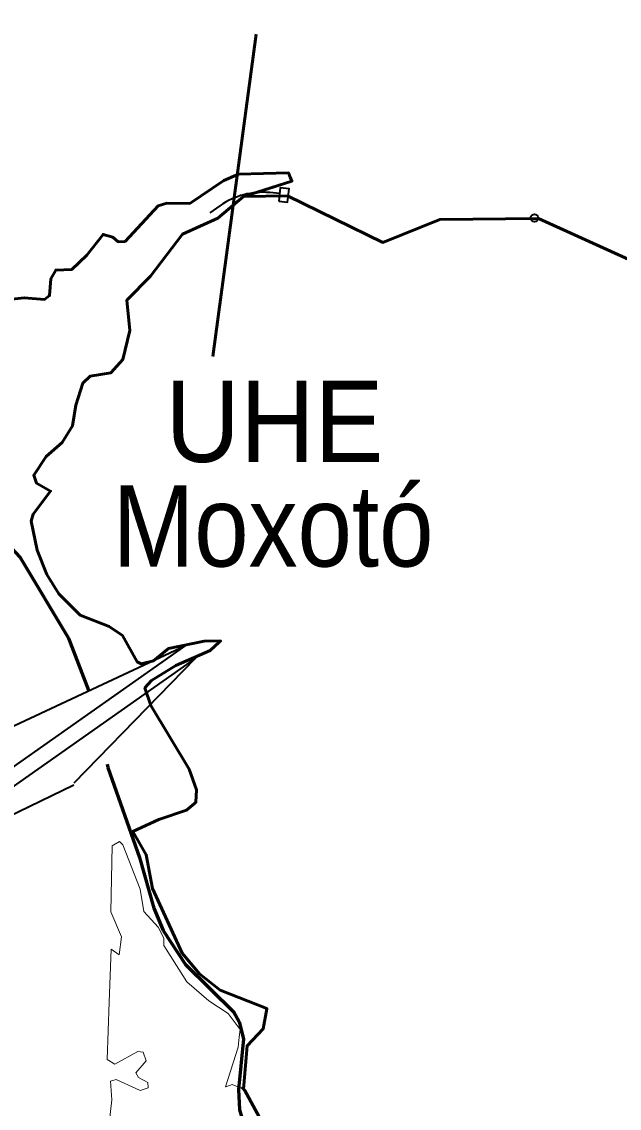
# Model space of a CAD drawing. Extents: x -1643653 to 4543381, y 1624270 to 13878484.
# Drawn here: x 587016 to 590692, y 8961924 to 8968607 of the extents above; entities that cross this region are included whole.
import ezdxf
from ezdxf.enums import TextEntityAlignment as Align

# ---------------------------------------------------------------- set-up
doc = ezdxf.new("R2010")
doc.units = 0
doc.header["$LTSCALE"] = 200
doc.linetypes.add('LONG_DASH_SHORT_DASH', pattern=[9.9, 6, -1.2, 1.5, -1.2])
for name, color, linetype, lineweight in [('1', 7, 'Continuous', 13), ('14', 7, 'Continuous', 13), ('25', 7, 'Continuous', 13), ('27', 7, 'Continuous', 53), ('28', 7, 'Continuous', 53), ('31', 7, 'Continuous', 53), ('60', 7, 'Continuous', 53), ('7', 7, 'LONG_DASH_SHORT_DASH', 60)]:
    doc.layers.add(name, color=color, linetype=linetype, lineweight=lineweight)
doc.layers.add('42', color=7, linetype='Continuous')

msp = doc.modelspace()

# ---------------------------------------------------------------- linework, layer by layer
at = {"layer": '1', "lineweight": 25}
msp.add_spline([(814781, 9009175.5), (814787.2, 9009173.4), (814796.9, 9009173.4), (814799.4, 9009172.4), (814805.1, 9009174.5), (814805.6, 9009176.5), (814811.7, 9009179.5), (814811.7, 9009179.5), (814801.5, 9009181), (814790.7, 9009181.5), (814784.1, 9009183.1), (814777.4, 9009185.1), (814778.4, 9009175.5)], degree=3, dxfattribs=at)
at = {"layer": '14', "lineweight": 40}
for p, q in [((588601.8, 8967550.6), (588542, 8967555.7)), ((588235.6, 8967474.9), (588172.7, 8967431.9))]:
    msp.add_line(p, q, dxfattribs=at)
msp.add_arc((588497.5, 8967102.9), 455, 84.39529, 125.14872, dxfattribs=at)
at = {"layer": '25', "lineweight": 35}
for p, q in [((588022.6, 8964770.6), (586135.6, 8963442.6)), ((586940.7, 8964263.4), (588022.6, 8964770.6)), ((588084.7, 8964692), (586189.9, 8963358.5)), ((587339.3, 8963925.5), (588084.7, 8964692)), ((586189.9, 8963358.5), (587335.7, 8963913.8))]:
    msp.add_line(p, q, dxfattribs=at)
at = {"layer": '25'}
for points in [[(586938.3, 8966898.9), (587031.7, 8966909.6), (587155.3, 8966899.2), (587187, 8966922.6), (587195.6, 8967026.5), (587225.2, 8967079.4), (587325, 8967083.9), (587416.4, 8967171), (587516.5, 8967298.4), (587577.2, 8967281.7), (587609.8, 8967253.9), (587652.2, 8967256), (587856.2, 8967474.6), (587908.7, 8967491.8), (588049.3, 8967489.5), (588259.2, 8967631.5), (588349.7, 8967670.3), (588657.3, 8967677.5), (588667.8, 8967651.8)], [(586938.3, 8966898.9), (587031.7, 8966909.6), (587155.3, 8966899.2), (587187, 8966922.6), (587195.6, 8967026.5), (587225.2, 8967079.4), (587325, 8967083.9), (587416.4, 8967171), (587516.5, 8967298.4), (587577.2, 8967281.7), (587609.8, 8967253.9), (587652.2, 8967256), (587856.2, 8967474.6), (587908.7, 8967491.8), (588049.3, 8967489.5), (588259.2, 8967631.5), (588349.7, 8967670.3), (588657.3, 8967677.5), (588667.8, 8967651.8)], [(588667.8, 8967651.8), (588678.2, 8967626.5), (588381.1, 8967532.1), (588221.7, 8967398.4), (588005.1, 8967300.6), (587807.3, 8967041.3), (587663.1, 8966894.9), (587682, 8966707.8), (587637.4, 8966529.4), (587563.2, 8966446.7), (587438, 8966427.4), (587392.7, 8966384.2), (587348.6, 8966249.6), (587329.2, 8966121.3), (587265.6, 8966019.6), (587165.8, 8965932.5), (587089.5, 8965818), (587106.5, 8965769), (587193.3, 8965719.9), (587087.2, 8965577.5), (587074.5, 8965534.6), (587110.7, 8965356.6), (587170.4, 8965207.5), (587244.3, 8965087.2), (587376.1, 8964957.5), (587554.3, 8964887.4), (587635.2, 8964832.1), (587726.7, 8964670.8), (587750.6, 8964658), (587826.4, 8964675), (587917.9, 8964751.3), (588138.8, 8964796.3), (588239.8, 8964798.6), (588239.8, 8964798.6), (588231, 8964790.9)], [(588667.8, 8967651.8), (588678.2, 8967626.5), (588381.1, 8967532.1), (588221.7, 8967398.4), (588005.1, 8967300.6), (587807.3, 8967041.3), (587663.1, 8966894.9), (587682, 8966707.8), (587637.4, 8966529.4), (587563.2, 8966446.7), (587438, 8966427.4), (587392.7, 8966384.2), (587348.6, 8966249.6), (587329.2, 8966121.3), (587265.6, 8966019.6), (587165.8, 8965932.5), (587089.5, 8965818), (587106.5, 8965769), (587193.3, 8965719.9), (587087.2, 8965577.5), (587074.5, 8965534.6), (587110.7, 8965356.6), (587170.4, 8965207.5), (587244.3, 8965087.2), (587376.1, 8964957.5), (587554.3, 8964887.4), (587635.2, 8964832.1), (587678.5, 8964757.6)], [(588231, 8964790.9), (588174.2, 8964740.5), (587964.7, 8964647.4), (587813.9, 8964556), (587773.6, 8964509.6), (587809.5, 8964400.9), (588045.3, 8964009.8), (588090.5, 8963883.4), (588087.9, 8963805.8), (588079.5, 8963798.7)], [(587773.6, 8964509.6), (587809.5, 8964400.9), (588045.3, 8964009.8), (588090.5, 8963883.4), (588087.9, 8963805.8), (588079.5, 8963798.7)], [(588079.5, 8963798.7), (588030.2, 8963757.2), (587858.5, 8963700), (587699.1, 8963625.3), (587781.9, 8963483), (587820, 8963275.3), (588002, 8962877.1), (588002, 8962877.1), (588108.8, 8962750.5), (588236.2, 8962650.7), (588523, 8962536.8)], [(588079.5, 8963798.7), (588030.2, 8963757.2), (587858.5, 8963700), (587699.1, 8963625.3), (587781.9, 8963483), (587820, 8963275.3), (588002, 8962877.1), (588002, 8962877.1), (588108.8, 8962750.5), (588236.2, 8962650.7), (588523, 8962536.8)], [(587982.8, 8962779.3), (587890.3, 8962924.4), (587890.1, 8962969.1), (587856.3, 8963036.9), (587766.9, 8963135.1), (587743.6, 8963270.8), (587637.1, 8963543.2), (587617, 8963563.8), (587571.7, 8963538.4), (587565.1, 8963131.3), (587628.8, 8962977.9), (587616.1, 8962866.9), (587565.4, 8962902.1), (587554.1, 8962576.4)], [(587982.8, 8962779.3), (587890.3, 8962924.4), (587890.1, 8962969.1), (587856.3, 8963036.9), (587766.9, 8963135.1), (587743.6, 8963270.8), (587637.1, 8963543.2), (587617, 8963563.8), (587571.7, 8963538.4), (587565.1, 8963131.3), (587628.8, 8962977.9), (587616.1, 8962866.9), (587565.4, 8962902.1), (587554.1, 8962576.4)], [(588354.5, 8962361.1), (588359.4, 8962408.8), (588285.5, 8962505.9), (588167, 8962584.2), (588032.3, 8962701.8), (587982.8, 8962779.3)], [(588354.5, 8962361.1), (588359.4, 8962408.8), (588285.5, 8962505.9), (588167, 8962584.2), (588032.3, 8962701.8), (587982.8, 8962779.3)], [(587554.1, 8962576.4), (587541.8, 8962223.9), (587588.7, 8962196), (587730.7, 8962272.2), (587762.7, 8962269), (587781.7, 8962215.1)], [(587554.1, 8962576.4), (587541.8, 8962223.9), (587588.7, 8962196), (587730.7, 8962272.2), (587762.7, 8962269), (587781.7, 8962215.1)], [(588523, 8962536.8), (588524.4, 8962536.2), (588501.9, 8962412.8), (588402.2, 8962308.3), (588381.1, 8962040.8), (588376.4, 8962042.8)], [(588523, 8962536.8), (588524.4, 8962536.2), (588501.9, 8962412.8), (588402.2, 8962308.3), (588381.1, 8962040.8), (588376.4, 8962042.8)], [(588271.6, 8962055.8), (588270.1, 8962055.2), (588348.1, 8962299.3), (588354.5, 8962361.1)], [(588271.6, 8962055.8), (588270.1, 8962055.2), (588348.1, 8962299.3), (588354.5, 8962361.1)], [(587781.7, 8962215.1), (587781.7, 8962215.1), (587718.2, 8962140.9), (587735, 8962113.3), (587792.4, 8962083.3), (587794.6, 8962050), (587745.5, 8962032.4), (587597.2, 8962100.2), (587563.1, 8962089.5), (587569.5, 8961975.7), (587540.2, 8961707.3), (587517.7, 8961501.6)], [(587781.7, 8962215.1), (587781.7, 8962215.1), (587718.2, 8962140.9), (587735, 8962113.3), (587792.4, 8962083.3), (587794.6, 8962050), (587745.5, 8962032.4), (587597.2, 8962100.2), (587563.1, 8962089.5), (587569.5, 8961975.7), (587540.2, 8961707.3), (587517.7, 8961501.6)], [(588376.4, 8962042.8), (588311.2, 8962069.4), (588271.6, 8962055.8), (588271.7, 8962060.3), (588271.6, 8962055.8)], [(588376.4, 8962042.8), (588311.2, 8962069.4), (588271.6, 8962055.8), (588271.7, 8962060.3), (588271.6, 8962055.8)]]:
    msp.add_lwpolyline(points, dxfattribs=at)
at = {"layer": '27'}
msp.add_line((592102.6, 8966532.4), (590195.5, 8967396.1), dxfattribs=at)
for points in [[(588667.8, 8967651.8), (588657.3, 8967677.5), (588349.7, 8967670.3), (588259.2, 8967631.5), (588049.3, 8967489.5), (587908.7, 8967491.8), (587856.2, 8967474.6), (587652.2, 8967256), (587609.8, 8967253.9), (587577.2, 8967281.7), (587516.5, 8967298.4), (587416.4, 8967171), (587325, 8967083.9), (587225.2, 8967079.4), (587195.6, 8967026.5), (587187, 8966922.6), (587155.3, 8966899.2), (587031.7, 8966909.6), (586938.3, 8966898.9)], [(588381.5, 8967532.2), (588678.2, 8967626.5), (588667.8, 8967651.8)], [(588239.8, 8964798.6), (588138.8, 8964796.3), (587917.9, 8964751.3), (587826.4, 8964675), (587750.6, 8964658), (587726.7, 8964670.8), (587635.2, 8964832.1), (587554.3, 8964887.4), (587376.1, 8964957.5), (587244.3, 8965087.2), (587170.4, 8965207.5), (587110.7, 8965356.6), (587074.5, 8965534.6), (587087.2, 8965577.5), (587193.3, 8965719.9), (587106.5, 8965769), (587089.5, 8965818), (587165.8, 8965932.5), (587265.6, 8966019.6), (587329.2, 8966121.3), (587348.6, 8966249.6), (587392.7, 8966384.2), (587438, 8966427.4), (587563.2, 8966446.7), (587637.4, 8966529.4), (587682, 8966707.8), (587663.1, 8966894.9), (587807.3, 8967041.3), (588005.1, 8967300.6), (588221.7, 8967398.4), (588381.1, 8967532.1), (588381.5, 8967532.2)], [(588381.5, 8967532.2), (588651.1, 8967535.2), (589236.5, 8967249.2), (589588.5, 8967391.6), (590195.5, 8967396.1), (592102.6, 8966532.4)], [(590195.5, 8967396.1), (589588.5, 8967391.6), (589236.5, 8967249.2), (588651.1, 8967535.2), (588381.5, 8967532.4)], [(588079.5, 8963798.7), (588087.9, 8963805.8), (588090.5, 8963883.4), (588045.3, 8964009.8), (587809.5, 8964400.9), (587773.6, 8964509.6), (587813.9, 8964556), (587964.7, 8964647.4), (588174.2, 8964740.5), (588231, 8964790.9), (588239.8, 8964798.6)], [(588523, 8962536.8), (588236.2, 8962650.7), (588108.8, 8962750.5), (588002, 8962877.1), (588002, 8962877.1), (587820, 8963275.3), (587781.9, 8963483), (587699.1, 8963625.3), (587858.5, 8963700), (588030.2, 8963757.2), (588079.5, 8963798.7)], [(588381.1, 8962040.8), (588402.2, 8962308.3), (588501.9, 8962412.8), (588524.4, 8962536.2), (588523, 8962536.8)], [(587368.2, 8959365.5), (587437, 8959830.7), (587541.6, 8960215), (587558.8, 8960425), (587596.7, 8960558.6), (587717.4, 8960723.2), (588213.5, 8961217.2), (588323.7, 8961300.9), (588630.6, 8961421.7), (588681.9, 8961493.8), (588387.5, 8962034), (588373.5, 8962049.1), (588381.1, 8962040.8)]]:
    msp.add_lwpolyline(points, dxfattribs=at)
at = {"layer": '28'}
for points in [[(586938.3, 8966898.9), (587031.7, 8966909.6), (587155.3, 8966899.2), (587187, 8966922.6), (587195.6, 8967026.5), (587225.2, 8967079.4), (587325, 8967083.9), (587416.4, 8967171), (587516.5, 8967298.4), (587577.2, 8967281.7), (587609.8, 8967253.9), (587652.2, 8967256), (587856.2, 8967474.6), (587908.7, 8967491.8), (588049.3, 8967489.5), (588259.2, 8967631.5), (588349.7, 8967670.3), (588657.3, 8967677.5), (588667.8, 8967651.8)], [(586938.3, 8966898.9), (587031.7, 8966909.6), (587155.3, 8966899.2), (587187, 8966922.6), (587195.6, 8967026.5), (587225.2, 8967079.4), (587325, 8967083.9), (587416.4, 8967171), (587516.5, 8967298.4), (587577.2, 8967281.7), (587609.8, 8967253.9), (587652.2, 8967256), (587856.2, 8967474.6), (587908.7, 8967491.8), (588049.3, 8967489.5), (588259.2, 8967631.5), (588349.7, 8967670.3), (588657.3, 8967677.5), (588667.8, 8967651.8)], [(588667.8, 8967651.8), (588678.2, 8967626.5), (588381.1, 8967532.1), (588221.7, 8967398.4), (588005.1, 8967300.6), (587807.3, 8967041.3), (587663.1, 8966894.9), (587682, 8966707.8), (587637.4, 8966529.4), (587563.2, 8966446.7), (587438, 8966427.4), (587392.7, 8966384.2), (587348.6, 8966249.6), (587329.2, 8966121.3), (587265.6, 8966019.6), (587165.8, 8965932.5), (587089.5, 8965818), (587106.5, 8965769), (587193.3, 8965719.9), (587087.2, 8965577.5), (587074.5, 8965534.6), (587110.7, 8965356.6), (587170.4, 8965207.5), (587244.3, 8965087.2), (587376.1, 8964957.5), (587554.3, 8964887.4), (587635.2, 8964832.1), (587726.7, 8964670.8), (587750.6, 8964658), (587826.4, 8964675), (587917.9, 8964751.3), (588138.8, 8964796.3), (588239.8, 8964798.6), (588239.8, 8964798.6), (588231, 8964790.9)], [(588667.8, 8967651.8), (588678.2, 8967626.5), (588381.1, 8967532.1), (588221.7, 8967398.4), (588005.1, 8967300.6), (587807.3, 8967041.3), (587663.1, 8966894.9), (587682, 8966707.8), (587637.4, 8966529.4), (587563.2, 8966446.7), (587438, 8966427.4), (587392.7, 8966384.2), (587348.6, 8966249.6), (587329.2, 8966121.3), (587265.6, 8966019.6), (587165.8, 8965932.5), (587089.5, 8965818), (587106.5, 8965769), (587193.3, 8965719.9), (587087.2, 8965577.5), (587074.5, 8965534.6), (587110.7, 8965356.6), (587170.4, 8965207.5), (587244.3, 8965087.2), (587376.1, 8964957.5), (587554.3, 8964887.4), (587635.2, 8964832.1), (587726.7, 8964670.8), (587750.6, 8964658), (587826.4, 8964675), (587917.9, 8964751.3), (588138.8, 8964796.3), (588239.8, 8964798.6), (588239.8, 8964798.6), (588231, 8964790.9)], [(588231, 8964790.9), (588174.2, 8964740.5), (587964.7, 8964647.4), (587813.9, 8964556), (587773.6, 8964509.6), (587809.5, 8964400.9), (588045.3, 8964009.8), (588090.5, 8963883.4), (588087.9, 8963805.8), (588079.5, 8963798.7)], [(588231, 8964790.9), (588174.2, 8964740.5), (587964.7, 8964647.4), (587813.9, 8964556), (587773.6, 8964509.6), (587809.5, 8964400.9), (588045.3, 8964009.8), (588090.5, 8963883.4), (588087.9, 8963805.8), (588079.5, 8963798.7)], [(588079.5, 8963798.7), (588030.2, 8963757.2), (587858.5, 8963700), (587699.1, 8963625.3), (587781.9, 8963483), (587820, 8963275.3), (588002, 8962877.1), (588002, 8962877.1), (588108.8, 8962750.5), (588236.2, 8962650.7), (588523, 8962536.8)], [(588079.5, 8963798.7), (588030.2, 8963757.2), (587858.5, 8963700), (587699.1, 8963625.3), (587781.9, 8963483), (587820, 8963275.3), (588002, 8962877.1), (588002, 8962877.1), (588108.8, 8962750.5), (588236.2, 8962650.7), (588523, 8962536.8)], [(588523, 8962536.8), (588524.4, 8962536.2), (588501.9, 8962412.8), (588402.2, 8962308.3), (588381.1, 8962040.8), (588373.5, 8962049.1)], [(588523, 8962536.8), (588524.4, 8962536.2), (588501.9, 8962412.8), (588402.2, 8962308.3), (588381.1, 8962040.8), (588373.5, 8962049.1)], [(588373.5, 8962049.1), (588387.5, 8962034), (588681.9, 8961493.8), (588630.6, 8961421.7), (588323.7, 8961300.9), (588213.5, 8961217.2), (587717.4, 8960723.2), (587596.7, 8960558.6), (587558.8, 8960425), (587541.6, 8960215), (587437, 8959830.7), (587368.2, 8959365.5)], [(588373.5, 8962049.1), (588387.5, 8962034), (588681.9, 8961493.8), (588630.6, 8961421.7), (588323.7, 8961300.9), (588213.5, 8961217.2), (587717.4, 8960723.2), (587596.7, 8960558.6), (587558.8, 8960425), (587541.6, 8960215), (587437, 8959830.7), (587368.2, 8959365.5)]]:
    msp.add_lwpolyline(points, dxfattribs=at)
at = {"layer": '31'}
msp.add_line((588192, 8966548.9), (588458, 8968531.1), dxfattribs=at)
at = {"layer": '60', "lineweight": 40}
msp.add_lwpolyline([(588596.7, 8967502.8), (588651.7, 8967496.8), (588660.6, 8967578.5), (588605.6, 8967584.5)], close=True, dxfattribs=at)
msp.add_circle((590170.3, 8967400), 23.4, dxfattribs=at)
at = {"layer": '7'}
for points in [[(583174.4, 8969966), (583327.9, 8969505.4), (583474.7, 8969160.4), (583725.5, 8968684.8), (583883.2, 8968539.9), (583982.9, 8968403.5), (584146.9, 8968235.1), (584624.8, 8967616.6), (584992.2, 8967072.1), (585186.8, 8966825.7), (585377.2, 8966655.9), (585748.8, 8966438.6), (585960.5, 8966257.3), (586351.6, 8965976.8), (586551, 8965796.4), (587006.6, 8965310.9), (587303.1, 8964815.2), (587426.7, 8964495.3)], [(587540.9, 8964040.5), (587545.5, 8964019), (587739.9, 8963466), (587828.5, 8963155), (587886.8, 8963016.8), (588023, 8962809.1), (588321.3, 8962515.1), (588353.7, 8962454.8), (588379.7, 8962350), (588349.5, 8962039.7), (588356.1, 8961913.4), (588409.9, 8961732.7), (588515.9, 8961598.5), (588533, 8961520.2), (588511.4, 8961464.3), (588140, 8961216), (587908.2, 8961023.1), (587733.4, 8960846.2), (587616.5, 8960660), (587498.3, 8960337.4), (587362.2, 8959603), (587314, 8959147.2), (587303.2, 8958935.8), (587310.7, 8958873)]]:
    msp.add_lwpolyline(points, dxfattribs=at)

# ---------------------------------------------------------------- texts
at = {"layer": '42'}
for s, width, p in [('UHE', 0.95, (588571.1, 8965899.4)), ('Moxotó', 0.9, (588562.6, 8965256.2))]:
    msp.add_text(s, height=500, dxfattribs=dict(at, width=width)).set_placement(p, align=Align.CENTER)

doc.saveas('drawing.dxf')
